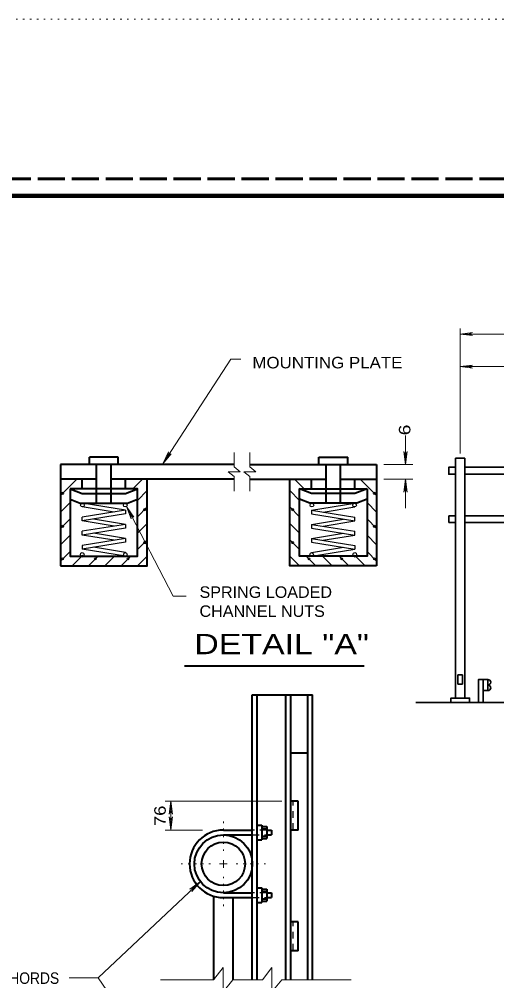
# Model space of a CAD drawing. Extents: x 312583 to 312854, y 144419 to 144597.
# Drawn here: x 312675.5 to 312707.1, y 144533.1 to 144596.8 of the extents above; entities that cross this region are included whole.
import ezdxf
from ezdxf.enums import TextEntityAlignment as Align

# ---------------------------------------------------------------- set-up
doc = ezdxf.new("R2010")
doc.units = 0
doc.header["$LTSCALE"] = 0.3
doc.header["$PDMODE"] = 32
doc.header["$PDSIZE"] = 0.15
for name, pattern in [('DOTTED', [1.5, 0.3, -1.2]), ('LONG_DASHED', [7.5, 6, -1.5]), ('SHORT_DASHED', [2.7, 1.5, -1.2])]:
    doc.linetypes.add(name, pattern=pattern)
doc.layers.add('1', color=7, linetype='Continuous', lineweight=13)
doc.layers.add('63', color=7, linetype='DOTTED', lineweight=13)

msp = doc.modelspace()

# ---------------------------------------------------------------- linework, layer by layer
at = {"layer": '1', "linetype": 'LONG_DASHED', "lineweight": 60}
msp.add_line((312851.75, 144586.2246), (312583.526, 144586.2246), dxfattribs=at)
at = {"layer": '1', "lineweight": 158}
msp.add_line((312616.5, 144585.0846), (312849, 144585.0846), dxfattribs=at)
at = {"layer": '1'}
for p, q in [((312704.6826, 144568.0337), (312704.6826, 144576.2983)), ((312704.6826, 144575.938), (312705.4953, 144576.0453)), ((312704.6826, 144575.938), (312732.1753, 144575.938)), ((312704.6826, 144575.938), (312705.4953, 144575.8383)), ((312705.4953, 144576.0453), (312705.2346, 144575.938)), ((312705.4953, 144575.8383), (312705.2346, 144575.938)), ((312704.6826, 144573.7837), (312705.4953, 144573.8833)), ((312704.6826, 144573.7837), (312721.1736, 144573.7837)), ((312704.6826, 144573.7837), (312705.4953, 144573.684)), ((312705.4953, 144573.8833), (312705.2346, 144573.7837)), ((312705.4953, 144573.684), (312705.2346, 144573.7837)), ((312701.0617, 144567.2955), (312701.0617, 144569.2122)), ((312684.9778, 144567.3492), (312685.3611, 144568.1389)), ((312684.9778, 144567.3492), (312685.5451, 144568.0162)), ((312685.3611, 144568.1389), (312685.2998, 144567.8475)), ((312685.5451, 144568.0162), (312685.2998, 144567.8475)), ((312689.7005, 144567.1422), (312689.7005, 144568.1082)), ((312690.7492, 144567.1422), (312690.7492, 144568.1082)), ((312700.9543, 144568.1619), (312701.0617, 144567.8859)), ((312701.0617, 144567.2955), (312700.9543, 144568.1619)), ((312701.169, 144568.1619), (312701.0617, 144567.8859)), ((312701.0617, 144567.2955), (312701.169, 144568.1619)), ((312699.628, 144567.2955), (312701.5447, 144567.2955)), ((312678.2005, 144565.2409), (312679.2968, 144566.3372)), ((312678.2005, 144566.3219), (312678.2158, 144566.3372)), ((312682.5168, 144566.2989), (312682.5551, 144566.3372)), ((312682.9998, 144565.7009), (312683.6361, 144566.3372)), ((312689.7005, 144565.5399), (312689.7005, 144566.5059)), ((312690.7492, 144565.5399), (312690.7492, 144566.5059)), ((312694.3533, 144565.7009), (312693.7093, 144566.3372)), ((312694.8363, 144566.2989), (312694.798, 144566.3372)), ((312699.145, 144565.2409), (312698.0487, 144566.3372)), ((312699.145, 144566.3219), (312699.1373, 144566.3372)), ((312699.628, 144566.3372), (312701.5447, 144566.3372)), ((312701.0617, 144566.3372), (312700.9543, 144565.4709)), ((312701.0617, 144564.4205), (312701.0617, 144566.3372)), ((312701.0617, 144566.3372), (312701.169, 144565.4709)), ((312683.3141, 144564.9265), (312683.9505, 144565.5705)), ((312694.039, 144564.9265), (312693.395, 144565.5705)), ((312700.9543, 144565.4709), (312701.0617, 144565.7469)), ((312701.169, 144565.4709), (312701.0617, 144565.7469)), ((312678.2005, 144564.1522), (312678.8445, 144564.7962)), ((312699.145, 144564.1522), (312698.5087, 144564.7962)), ((312682.5852, 144564.5284), (312682.8771, 144563.709)), ((312682.5852, 144564.5284), (312683.0709, 144563.8068)), ((312682.8771, 144563.709), (312682.8466, 144564.0036)), ((312683.0709, 144563.8068), (312682.8466, 144564.0036)), ((312683.3141, 144563.8455), (312683.9505, 144564.4895)), ((312694.039, 144563.8455), (312693.395, 144564.4895)), ((312678.2005, 144563.0712), (312678.8445, 144563.7152)), ((312683.3141, 144562.7569), (312683.9505, 144563.4009)), ((312694.039, 144562.7569), (312693.395, 144563.4009)), ((312699.145, 144563.0712), (312698.5087, 144563.7152)), ((312678.2005, 144561.9902), (312678.8445, 144562.6265)), ((312683.3141, 144561.6759), (312683.9505, 144562.3199)), ((312694.039, 144561.6759), (312693.395, 144562.3199)), ((312699.145, 144561.9902), (312698.5087, 144562.6265)), ((312678.2005, 144560.9015), (312678.8445, 144561.5455)), ((312699.145, 144560.9015), (312698.5087, 144561.5455)), ((312678.9748, 144560.5872), (312679.6111, 144561.2312)), ((312680.0558, 144560.5872), (312680.6998, 144561.2312)), ((312681.1368, 144560.5872), (312681.7808, 144561.2312)), ((312682.2255, 144560.5872), (312682.8695, 144561.2312)), ((312683.3065, 144560.5872), (312683.9505, 144561.2312)), ((312694.039, 144560.5872), (312693.395, 144561.2312)), ((312695.1277, 144560.5872), (312694.4837, 144561.2312)), ((312696.2087, 144560.5872), (312695.5647, 144561.2312)), ((312697.2973, 144560.5872), (312696.6533, 144561.2312)), ((312698.3783, 144560.5872), (312697.7343, 144561.2312)), ((312692.858, 144545.0139), (312685.13, 144545.0139)), ((312685.5134, 144545.0139), (312685.406, 144544.1475)), ((312685.5134, 144545.0139), (312685.5134, 144543.0973)), ((312685.5134, 144545.0139), (312685.6207, 144544.1475)), ((312685.406, 144544.1475), (312685.5134, 144544.4235)), ((312685.6207, 144544.1475), (312685.5134, 144544.4235)), ((312685.406, 144543.9637), (312685.5134, 144543.6877)), ((312685.5134, 144543.0973), (312685.406, 144543.9637)), ((312685.6207, 144543.9637), (312685.5134, 144543.6877)), ((312685.5134, 144543.0973), (312685.6207, 144543.9637)), ((312687.614, 144543.0973), (312685.13, 144543.0973)), ((312688.994, 144540.8586), (312688.994, 144541.1116)), ((312688.994, 144540.8586), (312688.741, 144540.8586)), ((312688.994, 144540.8586), (312689.247, 144540.8586)), ((312688.994, 144540.8586), (312688.994, 144540.6056)), ((312687.4684, 144539.7009), (312686.763, 144539.1873)), ((312686.763, 144539.1873), (312687.039, 144539.2946)), ((312687.4684, 144539.7009), (312686.9087, 144539.0263)), ((312686.9087, 144539.0263), (312687.039, 144539.2946)), ((312680.6987, 144533.3146), (312687.3227, 144523.7849)), ((312688.35, 144533.1919), (312684.8387, 144533.1919))]:
    msp.add_line(p, q, dxfattribs=at)
at = {"layer": '1', "lineweight": 40}
for p, q in [((312678.2005, 144567.2955), (312678.2005, 144560.5872)), ((312689.7005, 144567.2955), (312678.2005, 144567.2955)), ((312682.0338, 144567.7785), (312680.1171, 144567.7785)), ((312680.1171, 144567.2955), (312680.1171, 144567.7785)), ((312680.6001, 144564.7349), (312680.6001, 144567.2955)), ((312681.5585, 144564.7349), (312681.5585, 144567.2955)), ((312682.0338, 144567.2955), (312682.0338, 144567.7785)), ((312695.3117, 144567.7785), (312697.2283, 144567.7785)), ((312695.3117, 144567.2955), (312695.3117, 144567.7785)), ((312695.7947, 144564.7349), (312695.7947, 144567.2955)), ((312696.753, 144564.7349), (312696.753, 144567.2955)), ((312697.2283, 144567.2955), (312697.2283, 144567.7785)), ((312699.145, 144567.2955), (312699.145, 144560.5872)), ((312680.6001, 144566.3372), (312678.2005, 144566.3372)), ((312679.6418, 144565.7009), (312679.6418, 144566.3372)), ((312689.7005, 144566.3372), (312681.5585, 144566.3372)), ((312682.5168, 144565.7009), (312682.5168, 144566.3372)), ((312694.8363, 144565.7009), (312694.8363, 144566.3372)), ((312696.753, 144566.3372), (312699.145, 144566.3372)), ((312697.7113, 144565.7009), (312697.7113, 144566.3372)), ((312678.8445, 144565.0109), (312679.5191, 144564.7349)), ((312679.5191, 144564.7349), (312682.6395, 144564.7349)), ((312682.6395, 144564.7349), (312683.3141, 144565.0109)), ((312694.7137, 144564.7349), (312694.039, 144565.0109)), ((312697.834, 144564.7349), (312694.7137, 144564.7349)), ((312698.5087, 144565.0109), (312697.834, 144564.7349)), ((312686.4268, 144553.9619), (312698.3255, 144553.9619)), ((312690.9107, 144533.1919), (312690.9107, 144552.0443)), ((312690.9107, 144552.0443), (312694.905, 144552.0443)), ((312691.225, 144533.1919), (312691.225, 144552.0443)), ((312693.1417, 144533.1919), (312693.1417, 144552.0443)), ((312693.4637, 144533.1919), (312693.4637, 144552.0443)), ((312694.583, 144533.1919), (312694.583, 144552.0443)), ((312694.905, 144533.1919), (312694.905, 144552.0443)), ((312693.4637, 144548.2109), (312694.583, 144548.2109)), ((312693.9467, 144545.0139), (312693.4637, 144545.0139)), ((312693.9467, 144543.0973), (312693.9467, 144545.0139)), ((312688.994, 144543.0973), (312690.9107, 144543.0973)), ((312691.225, 144543.4193), (312691.547, 144543.4193)), ((312691.547, 144543.4193), (312691.547, 144542.4609)), ((312691.547, 144543.3349), (312691.869, 144543.3349)), ((312691.547, 144543.1739), (312691.869, 144543.1739)), ((312691.869, 144543.3349), (312691.869, 144542.5376)), ((312691.869, 144543.0973), (312692.1834, 144543.0973)), ((312692.1834, 144543.0973), (312692.1834, 144542.7753)), ((312693.9467, 144543.0973), (312693.4637, 144543.0973)), ((312688.994, 144542.7753), (312690.9107, 144542.7753)), ((312691.225, 144542.4609), (312691.547, 144542.4609)), ((312691.547, 144542.6986), (312691.869, 144542.6986)), ((312691.547, 144542.5376), (312691.869, 144542.5376)), ((312691.869, 144542.7753), (312692.1834, 144542.7753)), ((312691.225, 144539.2639), (312691.547, 144539.2639)), ((312691.547, 144539.2639), (312691.547, 144538.3056)), ((312691.547, 144539.1796), (312691.869, 144539.1796)), ((312691.869, 144539.1796), (312691.869, 144538.3823)), ((312688.35, 144538.7196), (312688.35, 144533.1919)), ((312688.994, 144538.9419), (312690.9107, 144538.9419)), ((312688.994, 144538.6276), (312690.9107, 144538.6276)), ((312689.6304, 144538.6276), (312689.6304, 144533.1919)), ((312691.547, 144539.0263), (312691.869, 144539.0263)), ((312691.547, 144538.5433), (312691.869, 144538.5433)), ((312691.869, 144538.9419), (312692.1834, 144538.9419)), ((312691.869, 144538.6276), (312692.1834, 144538.6276)), ((312692.1834, 144538.9419), (312692.1834, 144538.6276)), ((312691.225, 144538.3056), (312691.547, 144538.3056)), ((312691.547, 144538.3823), (312691.869, 144538.3823)), ((312693.9467, 144537.0253), (312693.4637, 144537.0253)), ((312693.9467, 144535.1086), (312693.9467, 144537.0253)), ((312693.9467, 144535.1086), (312693.4637, 144535.1086))]:
    msp.add_line(p, q, dxfattribs=at)
at = {"layer": '1', "lineweight": 35}
for p, q in [((312704.3759, 144551.8417), (312704.3759, 144567.727)), ((312704.3759, 144567.727), (312704.9893, 144567.727)), ((312704.9893, 144551.8417), (312704.9893, 144567.727)), ((312704.9893, 144567.1213), (312732.1753, 144567.1213)), ((312704.9893, 144566.6613), (312732.1753, 144566.6613)), ((312703.9159, 144563.909), (312703.9159, 144563.4567)), ((312704.3759, 144563.909), (312703.9159, 144563.909)), ((312704.3759, 144563.4567), (312703.9159, 144563.4567)), ((312704.9893, 144563.909), (312732.1753, 144563.909)), ((312704.9893, 144563.4567), (312732.1753, 144563.4567)), ((312704.8359, 144553.375), (312704.5293, 144553.375)), ((312704.5293, 144552.7617), (312704.5293, 144553.375)), ((312704.8359, 144552.7617), (312704.8359, 144553.375)), ((312704.8359, 144552.7617), (312704.5293, 144552.7617)), ((312706.2083, 144553.0683), (312706.2083, 144551.5427)), ((312706.5149, 144553.0683), (312706.5149, 144552.3323)), ((312706.2083, 144552.3323), (312706.5149, 144552.3323)), ((312710.1796, 144551.5427), (312701.7309, 144551.5427))]:
    msp.add_line(p, q, dxfattribs=at)
at = {"layer": '1', "lineweight": 25}
for p, q in [((312682.5168, 144564.2749), (312679.6418, 144564.7425)), ((312694.8363, 144564.2749), (312697.7113, 144564.7425)), ((312681.7578, 144564.1522), (312679.6418, 144564.4972)), ((312682.5168, 144564.2749), (312679.6418, 144563.8072)), ((312682.5168, 144564.0295), (312679.6418, 144563.5619)), ((312682.5168, 144564.2749), (312682.5168, 144564.0295)), ((312694.8363, 144564.2749), (312697.7113, 144563.8072)), ((312694.8363, 144564.2749), (312694.8363, 144564.0295)), ((312694.8363, 144564.0295), (312697.7113, 144563.5619)), ((312695.5953, 144564.1522), (312697.7113, 144564.4972)), ((312679.6418, 144563.5619), (312679.6418, 144563.8072)), ((312681.7578, 144563.2169), (312679.6418, 144563.5619)), ((312682.5168, 144563.3395), (312680.4008, 144563.6845)), ((312694.8363, 144563.3395), (312696.9523, 144563.6845)), ((312695.5953, 144563.2169), (312697.7113, 144563.5619)), ((312697.7113, 144563.5619), (312697.7113, 144563.8072)), ((312682.5168, 144563.3395), (312679.6418, 144562.8795)), ((312682.5168, 144563.0942), (312679.6418, 144562.6342)), ((312679.6418, 144562.6342), (312679.6418, 144562.8795)), ((312682.5168, 144562.4119), (312680.4008, 144562.7569)), ((312682.5168, 144563.3395), (312682.5168, 144563.0942)), ((312694.8363, 144563.3395), (312697.7113, 144562.8795)), ((312694.8363, 144563.3395), (312694.8363, 144563.0942)), ((312694.8363, 144563.0942), (312697.7113, 144562.6342)), ((312694.8363, 144562.4119), (312696.9523, 144562.7569)), ((312697.7113, 144562.6342), (312697.7113, 144562.8795)), ((312681.7578, 144562.2892), (312679.6418, 144562.6342)), ((312682.5168, 144562.4119), (312679.6418, 144561.9442)), ((312682.5168, 144562.1665), (312679.6418, 144561.6989)), ((312682.5168, 144562.4119), (312682.5168, 144562.1665)), ((312694.8363, 144562.4119), (312697.7113, 144561.9442)), ((312694.8363, 144562.4119), (312694.8363, 144562.1665)), ((312694.8363, 144562.1665), (312697.7113, 144561.6989)), ((312695.5877, 144562.2892), (312697.7113, 144562.6342)), ((312679.6418, 144561.9442), (312679.6418, 144561.6989)), ((312682.5168, 144561.2312), (312679.6418, 144561.6989)), ((312682.5168, 144561.4765), (312680.3931, 144561.8215)), ((312694.8363, 144561.4765), (312696.9523, 144561.8215)), ((312694.8363, 144561.2312), (312697.7113, 144561.6989)), ((312697.7113, 144561.9442), (312697.7113, 144561.6989))]:
    msp.add_line(p, q, dxfattribs=at)
at = {"layer": '1', "linetype": 'SHORT_DASHED', "lineweight": 25}
for p, q in [((312693.6247, 144543.0973), (312693.6247, 144545.0139)), ((312691.869, 144543.0973), (312690.9107, 144543.0973)), ((312690.9107, 144542.7753), (312691.869, 144542.7753)), ((312691.869, 144538.9419), (312690.9107, 144538.9419)), ((312690.9107, 144538.6276), (312691.869, 144538.6276)), ((312693.6247, 144535.1086), (312693.6247, 144537.0253))]:
    msp.add_line(p, q, dxfattribs=at)
at = {"layer": '1', "linetype": 'DOTTED'}
for p, q in [((312688.994, 144541.7173), (312688.994, 144543.7489)), ((312688.1354, 144540.8586), (312686.1037, 144540.8586)), ((312689.845, 144540.8586), (312691.8844, 144540.8586)), ((312688.994, 144540.0076), (312688.994, 144537.9683))]:
    msp.add_line(p, q, dxfattribs=at)
at = {"layer": '1'}
for points in [[(312684.9778, 144567.3492), (312689.4875, 144574.2743), (312690.1423, 144574.2743)], [(312689.7005, 144567.1422), (312690.0991, 144566.8279), (312689.3018, 144566.8279), (312689.7005, 144566.5059)], [(312690.7492, 144567.1422), (312691.1479, 144566.8279), (312690.3505, 144566.8279), (312690.7492, 144566.5059)], [(312682.597, 144564.5095), (312685.6751, 144558.5758), (312686.5265, 144558.5758)], [(312678.782, 144533.3146), (312680.6987, 144533.3146), (312687.4684, 144539.7009)], [(312688.35, 144533.1919), (312688.9864, 144533.9893), (312688.9864, 144532.3946), (312689.6304, 144533.1919), (312691.5777, 144533.1919)], [(312691.5777, 144533.1919), (312692.214, 144533.9893), (312692.214, 144532.3946), (312692.858, 144533.1919), (312697.458, 144533.1919)]]:
    msp.add_lwpolyline(points, dxfattribs=at)
at = {"layer": '1', "lineweight": 40}
for points in [[(312690.7492, 144567.2955), (312692.7574, 144567.2955), (312699.145, 144567.2955)], [(312678.2005, 144560.5872), (312683.9505, 144560.5872), (312683.9505, 144566.3372)], [(312690.7492, 144566.3372), (312692.7574, 144566.3372), (312695.7947, 144566.3372)], [(312699.145, 144560.5872), (312693.395, 144560.5872), (312693.395, 144566.3372)], [(312678.8445, 144565.7009), (312679.6418, 144565.3789), (312682.5168, 144565.3789), (312683.3141, 144565.7009)], [(312698.5087, 144565.7009), (312697.7113, 144565.3789), (312694.8363, 144565.3789), (312694.039, 144565.7009)]]:
    msp.add_lwpolyline(points, dxfattribs=at)
at = {"layer": '1', "lineweight": 35}
for points in [[(312704.3759, 144567.1213), (312703.9159, 144567.1213), (312703.9159, 144566.6613), (312704.3759, 144566.6613)], [(312705.9016, 144551.5427), (312705.9016, 144553.0683), (312706.5149, 144553.0683)], [(312704.0693, 144551.5427), (312704.0693, 144551.8417), (312705.2959, 144551.8417), (312705.2959, 144551.5427)]]:
    msp.add_lwpolyline(points, dxfattribs=at)
at = {"layer": '1', "lineweight": 40}
for points in [[(312678.8445, 144565.7009), (312678.8445, 144561.2312), (312683.3141, 144561.2312), (312683.3141, 144565.7009)], [(312698.5087, 144565.7009), (312698.5087, 144561.2312), (312694.039, 144561.2312), (312694.039, 144565.7009)]]:
    msp.add_lwpolyline(points, close=True, dxfattribs=at)
at = {"layer": '1', "lineweight": 25}
for centre in [(312679.6605, 144564.618), (312682.4905, 144564.618), (312694.855, 144564.618), (312697.685, 144564.618), (312679.649, 144561.352), (312682.502, 144561.352), (312694.8435, 144561.352), (312697.6965, 144561.352)]:
    msp.add_circle(centre, 0.1213, dxfattribs=at)
at = {"layer": '1', "lineweight": 40}
for radius in [1.9167, 1.4375]:
    msp.add_circle((312688.9921, 144540.8599), radius, dxfattribs=at)
at = {"layer": '1', "lineweight": 35}
for centre in [(312706.5143, 144552.8838), (312706.5143, 144552.5172)]:
    msp.add_arc(centre, 0.1833, 270, 90, dxfattribs=at)
at = {"layer": '1', "lineweight": 40}
msp.add_arc((312688.9921, 144540.8599), 2.2361, 90, 270, dxfattribs=at)
at = {"layer": '1'}
for p in [(312678.3538, 144565.3865), (312698.9993, 144565.3865), (312683.7741, 144564.3055), (312693.579, 144564.3055), (312678.3538, 144563.2169), (312698.9993, 144563.2169), (312683.7741, 144562.1359), (312693.579, 144562.1359), (312678.3538, 144561.0549), (312679.6418, 144561.2312), (312680.5158, 144561.0549), (312682.6855, 144561.0549), (312694.66, 144561.0549), (312696.8297, 144561.0549), (312697.7113, 144561.2312), (312698.9993, 144561.0549)]:
    msp.add_point(p, dxfattribs=at)
at = {"layer": '63'}
msp.add_line((312601.2, 144596.7846), (312853.5, 144596.7846), dxfattribs=at)

# ---------------------------------------------------------------- texts
at = {"layer": '1'}
for s, width, p in [('MOUNTING PLATE', 1.1, (312690.9161, 144573.6678)), ('SPRING LOADED', 1.05, (312687.4137, 144558.4727)), ('CHANNEL NUTS', 1.05, (312687.4137, 144557.2127)), ('CHORDS', 0.9, (312674.154, 144532.914))]:
    msp.add_text(s, height=0.76, dxfattribs=dict(at, width=width)).set_placement(p)
for s, width, p in [(' 6 ', 1.25, (312701.38, 144568.8844)), ('76 ', 1.2, (312685.1775, 144543.3619))]:
    msp.add_text(s, height=0.76, rotation=90, dxfattribs=dict(at, width=width)).set_placement(p)
at = {"layer": '1', "width": 1.25}
msp.add_text('DETAIL "A"', height=1.342, dxfattribs=at).set_placement((312692.8515, 144554.7433), align=Align.CENTER)

doc.saveas('drawing.dxf')
